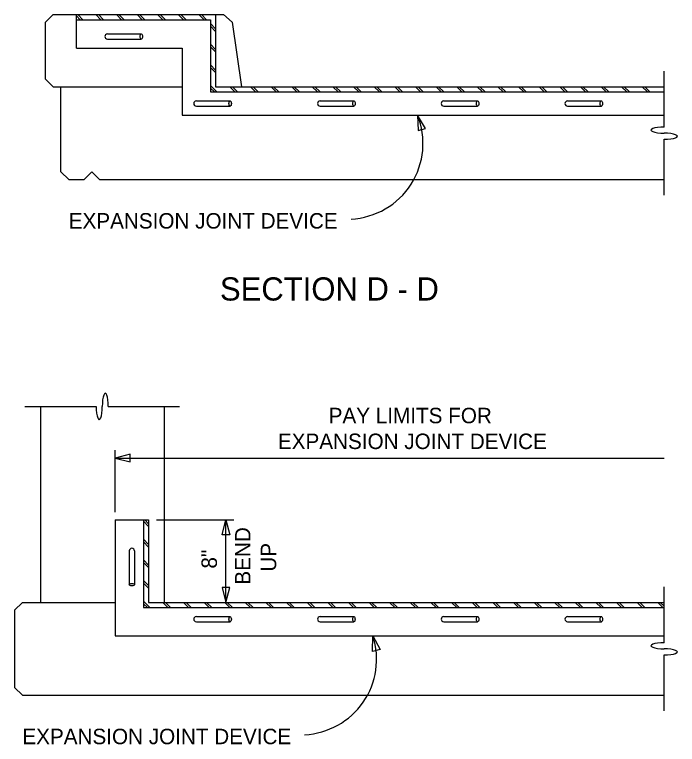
# Model space of a CAD drawing. Extents: x 19590 to 20151, y 19944 to 20103.
# Drawn here: x 19652.05 to 19671.87, y 20018.28 to 20040.1 of the extents above; entities that cross this region are included whole.
import ezdxf

# ---------------------------------------------------------------- set-up
doc = ezdxf.new("R2010")
doc.units = 0
for name, color, linetype in [('DETAIL_PR', 7, 'Continuous'), ('DETAIL_TEXT_DIMEN_PR', 7, 'Continuous'), ('Level 1', 7, 'Continuous')]:
    doc.layers.add(name, color=color, linetype=linetype)

msp = doc.modelspace()

# ---------------------------------------------------------------- linework, layer by layer
at = {"layer": 'DETAIL_PR'}
for p, q in [((19653.203, 20040.101), (19652.971, 20039.87)), ((19653.203, 20040.101), (19653.896, 20040.101)), ((19653.896, 20040.101), (19658.059, 20040.101)), ((19653.896, 20039.099), (19653.896, 20040.101)), ((19654.089, 20039.947), (19653.935, 20040.101)), ((19654.629, 20039.947), (19654.474, 20040.101)), ((19654.706, 20039.947), (19654.552, 20040.101)), ((19655.245, 20039.947), (19655.091, 20040.101)), ((19655.322, 20039.947), (19655.168, 20040.101)), ((19655.862, 20039.947), (19655.708, 20040.101)), ((19655.939, 20039.947), (19655.785, 20040.101)), ((19656.479, 20039.947), (19656.324, 20040.101)), ((19656.556, 20039.947), (19656.402, 20040.101)), ((19657.095, 20039.947), (19656.941, 20040.101)), ((19657.172, 20039.947), (19657.018, 20040.101)), ((19657.712, 20039.947), (19657.558, 20040.101)), ((19657.789, 20039.947), (19657.635, 20040.101)), ((19658.059, 20040.101), (19658.059, 20037.943)), ((19658.059, 20040.101), (19658.29, 20040.101)), ((19658.554, 20039.872), (19658.29, 20040.101)), ((19652.971, 20038.174), (19652.971, 20039.87)), ((19654.012, 20039.947), (19653.896, 20040.063)), ((19653.896, 20039.947), (19657.905, 20039.947)), ((19657.905, 20039.947), (19657.905, 20037.789)), ((19658.554, 20039.872), (19658.83, 20037.943)), ((19658.059, 20039.677), (19657.905, 20039.831)), ((19658.059, 20039.6), (19657.905, 20039.754)), ((19654.821, 20039.523), (19655.833, 20039.523)), ((19654.821, 20039.369), (19655.833, 20039.369)), ((19658.059, 20039.06), (19657.905, 20039.215)), ((19653.896, 20039.099), (19657.057, 20039.099)), ((19657.057, 20039.099), (19657.057, 20037.095)), ((19658.059, 20038.983), (19657.905, 20039.138)), ((19658.059, 20038.444), (19657.905, 20038.598)), ((19658.059, 20038.367), (19657.905, 20038.521)), ((19671.471, 20036.737), (19671.471, 20038.405)), ((19653.203, 20037.943), (19652.971, 20038.174)), ((19653.203, 20037.943), (19657.057, 20037.943)), ((19653.434, 20035.399), (19653.434, 20037.943)), ((19658.097, 20037.789), (19657.905, 20037.981)), ((19658.02, 20037.789), (19657.905, 20037.904)), ((19658.059, 20037.943), (19671.471, 20037.943)), ((19658.637, 20037.789), (19658.483, 20037.943)), ((19658.714, 20037.789), (19658.56, 20037.943)), ((19659.254, 20037.789), (19659.099, 20037.943)), ((19659.331, 20037.789), (19659.177, 20037.943)), ((19659.87, 20037.789), (19659.716, 20037.943)), ((19659.947, 20037.789), (19659.793, 20037.943)), ((19660.487, 20037.789), (19660.333, 20037.943)), ((19660.564, 20037.789), (19660.41, 20037.943)), ((19661.104, 20037.789), (19660.949, 20037.943)), ((19661.181, 20037.789), (19661.027, 20037.943)), ((19661.72, 20037.789), (19661.566, 20037.943)), ((19661.797, 20037.789), (19661.643, 20037.943)), ((19662.337, 20037.789), (19662.183, 20037.943)), ((19662.414, 20037.789), (19662.26, 20037.943)), ((19662.954, 20037.789), (19662.799, 20037.943)), ((19663.031, 20037.789), (19662.877, 20037.943)), ((19663.57, 20037.789), (19663.416, 20037.943)), ((19663.647, 20037.789), (19663.493, 20037.943)), ((19664.187, 20037.789), (19664.033, 20037.943)), ((19664.264, 20037.789), (19664.11, 20037.943)), ((19664.804, 20037.789), (19664.649, 20037.943)), ((19664.881, 20037.789), (19664.727, 20037.943)), ((19665.42, 20037.789), (19665.266, 20037.943)), ((19665.497, 20037.789), (19665.343, 20037.943)), ((19666.037, 20037.789), (19665.883, 20037.943)), ((19666.114, 20037.789), (19665.96, 20037.943)), ((19666.654, 20037.789), (19666.499, 20037.943)), ((19666.731, 20037.789), (19666.577, 20037.943)), ((19667.27, 20037.789), (19667.116, 20037.943)), ((19667.347, 20037.789), (19667.193, 20037.943)), ((19667.887, 20037.789), (19667.733, 20037.943)), ((19667.964, 20037.789), (19667.81, 20037.943)), ((19668.504, 20037.789), (19668.349, 20037.943)), ((19668.581, 20037.789), (19668.427, 20037.943)), ((19669.12, 20037.789), (19668.966, 20037.943)), ((19669.197, 20037.789), (19669.043, 20037.943)), ((19669.737, 20037.789), (19669.583, 20037.943)), ((19669.814, 20037.789), (19669.66, 20037.943)), ((19670.354, 20037.789), (19670.199, 20037.943)), ((19670.431, 20037.789), (19670.277, 20037.943)), ((19670.97, 20037.789), (19670.816, 20037.943)), ((19671.047, 20037.789), (19670.893, 20037.943)), ((19657.905, 20037.789), (19671.471, 20037.789)), ((19657.481, 20037.519), (19658.493, 20037.519)), ((19661.181, 20037.519), (19662.193, 20037.519)), ((19664.881, 20037.519), (19665.893, 20037.519)), ((19668.581, 20037.519), (19669.593, 20037.519)), ((19657.481, 20037.365), (19658.493, 20037.365)), ((19661.181, 20037.365), (19662.193, 20037.365)), ((19664.881, 20037.365), (19665.893, 20037.365)), ((19668.581, 20037.365), (19669.593, 20037.365)), ((19657.057, 20037.095), (19671.471, 20037.095)), ((19671.471, 20034.705), (19671.471, 20036.373)), ((19653.434, 20035.399), (19653.665, 20035.168)), ((19654.359, 20035.399), (19654.128, 20035.168)), ((19654.359, 20035.399), (19654.59, 20035.168)), ((19653.665, 20035.168), (19654.128, 20035.168)), ((19654.59, 20035.168), (19671.471, 20035.168)), ((19652.355, 20028.381), (19654.485, 20028.381)), ((19652.817, 20028.381), (19652.817, 20022.523)), ((19654.849, 20028.381), (19656.98, 20028.381)), ((19656.517, 20028.381), (19656.517, 20022.523)), ((19655.053, 20024.989), (19656.055, 20024.989)), ((19655.053, 20024.989), (19655.053, 20021.521)), ((19655.901, 20024.989), (19655.901, 20022.368)), ((19656.055, 20024.797), (19655.901, 20024.951)), ((19656.055, 20024.874), (19655.939, 20024.989)), ((19656.055, 20024.989), (19656.055, 20022.523)), ((19656.055, 20024.257), (19655.901, 20024.411)), ((19656.055, 20024.18), (19655.901, 20024.334)), ((19655.477, 20024.064), (19655.477, 20023.053)), ((19655.631, 20024.064), (19655.631, 20023.053)), ((19656.055, 20023.64), (19655.901, 20023.795)), ((19656.055, 20023.563), (19655.901, 20023.717)), ((19656.055, 20023.024), (19655.901, 20023.178)), ((19656.055, 20022.947), (19655.901, 20023.101)), ((19671.471, 20021.317), (19671.471, 20022.985)), ((19652.278, 20022.523), (19652.047, 20022.291)), ((19652.278, 20022.523), (19655.053, 20022.523)), ((19656.093, 20022.369), (19655.901, 20022.561)), ((19656.016, 20022.369), (19655.901, 20022.484)), ((19656.055, 20022.523), (19671.471, 20022.523)), ((19656.633, 20022.369), (19656.479, 20022.523)), ((19656.71, 20022.369), (19656.556, 20022.523)), ((19657.249, 20022.369), (19657.095, 20022.523)), ((19657.327, 20022.369), (19657.172, 20022.523)), ((19657.866, 20022.369), (19657.712, 20022.523)), ((19657.943, 20022.369), (19657.789, 20022.523)), ((19658.483, 20022.369), (19658.329, 20022.523)), ((19658.56, 20022.369), (19658.406, 20022.523)), ((19659.099, 20022.369), (19658.945, 20022.523)), ((19659.177, 20022.369), (19659.022, 20022.523)), ((19659.716, 20022.369), (19659.562, 20022.523)), ((19659.793, 20022.369), (19659.639, 20022.523)), ((19660.333, 20022.369), (19660.179, 20022.523)), ((19660.41, 20022.369), (19660.256, 20022.523)), ((19660.949, 20022.369), (19660.795, 20022.523)), ((19661.027, 20022.369), (19660.872, 20022.523)), ((19661.566, 20022.369), (19661.412, 20022.523)), ((19661.643, 20022.369), (19661.489, 20022.523)), ((19662.183, 20022.369), (19662.029, 20022.523)), ((19662.26, 20022.369), (19662.106, 20022.523)), ((19662.799, 20022.369), (19662.645, 20022.523)), ((19662.877, 20022.369), (19662.722, 20022.523)), ((19663.416, 20022.369), (19663.262, 20022.523)), ((19663.493, 20022.369), (19663.339, 20022.523)), ((19664.033, 20022.369), (19663.879, 20022.523)), ((19664.11, 20022.369), (19663.956, 20022.523)), ((19664.649, 20022.369), (19664.495, 20022.523)), ((19664.727, 20022.369), (19664.572, 20022.523)), ((19665.266, 20022.369), (19665.112, 20022.523)), ((19665.343, 20022.369), (19665.189, 20022.523)), ((19665.883, 20022.369), (19665.729, 20022.523)), ((19665.96, 20022.369), (19665.806, 20022.523)), ((19666.499, 20022.369), (19666.345, 20022.523)), ((19666.577, 20022.369), (19666.422, 20022.523)), ((19667.116, 20022.369), (19666.962, 20022.523)), ((19667.193, 20022.369), (19667.039, 20022.523)), ((19667.733, 20022.369), (19667.579, 20022.523)), ((19667.81, 20022.369), (19667.656, 20022.523)), ((19668.349, 20022.369), (19668.195, 20022.523)), ((19668.427, 20022.369), (19668.272, 20022.523)), ((19668.966, 20022.369), (19668.812, 20022.523)), ((19669.043, 20022.369), (19668.889, 20022.523)), ((19669.583, 20022.369), (19669.429, 20022.523)), ((19669.66, 20022.369), (19669.506, 20022.523)), ((19670.199, 20022.369), (19670.045, 20022.523)), ((19670.277, 20022.369), (19670.122, 20022.523)), ((19670.816, 20022.369), (19670.662, 20022.523)), ((19670.893, 20022.369), (19670.739, 20022.523)), ((19671.433, 20022.369), (19671.279, 20022.523)), ((19671.471, 20022.407), (19671.356, 20022.523)), ((19652.046, 20022.291), (19652.046, 20019.979)), ((19655.901, 20022.369), (19671.471, 20022.369)), ((19657.481, 20022.098), (19658.492, 20022.098)), ((19661.181, 20022.098), (19662.192, 20022.098)), ((19664.881, 20022.098), (19665.892, 20022.098)), ((19668.581, 20022.098), (19669.592, 20022.098)), ((19657.481, 20021.944), (19658.492, 20021.944)), ((19661.181, 20021.944), (19662.192, 20021.944)), ((19664.881, 20021.944), (19665.892, 20021.944)), ((19668.581, 20021.944), (19669.592, 20021.944)), ((19655.053, 20021.521), (19671.471, 20021.521)), ((19671.471, 20019.285), (19671.471, 20020.953)), ((19652.278, 20019.748), (19652.047, 20019.979)), ((19652.278, 20019.748), (19671.471, 20019.748))]:
    msp.add_line(p, q, dxfattribs=at)
for centre, start, end in [((19654.821, 20039.446), 90, 270), ((19657.481, 20037.442), 90, 270), ((19661.181, 20037.442), 90, 270), ((19664.881, 20037.442), 90, 270), ((19668.581, 20037.442), 90, 270), ((19655.554, 20024.064), 360, 180), ((19657.481, 20022.022), 90, 270), ((19661.181, 20022.022), 90, 270), ((19664.881, 20022.022), 90, 270), ((19668.581, 20022.022), 90, 270)]:
    msp.add_arc(centre, 0.0771, start, end, dxfattribs=at)
for centre, major_axis in [((19655.833, 20039.446), (0, 0.0773)), ((19658.493, 20037.442), (0, 0.0773)), ((19662.193, 20037.442), (0, 0.0773)), ((19665.893, 20037.442), (0, 0.0773)), ((19669.593, 20037.442), (0, 0.0773)), ((19655.554, 20023.053), (0.0773, 0)), ((19658.492, 20022.021), (0, 0.0773)), ((19662.192, 20022.021), (0, 0.0773)), ((19665.892, 20022.021), (0, 0.0773)), ((19669.592, 20022.021), (0, 0.0773))]:
    msp.add_ellipse(centre, major_axis=major_axis, ratio=0.466726, dxfattribs=at)
for centre, major_axis, ratio, start_param, end_param in [((19671.471, 20036.646), (0.395, 0), 0.230204, 1.570796, 4.712389), ((19671.471, 20036.464), (0.395, 0), 0.230206, 4.712389, 7.853982), ((19654.758, 20028.381), (0, -0.395), 0.230204, 1.570796, 4.712389), ((19654.576, 20028.381), (0, -0.395), 0.230206, 4.712389, 7.853982), ((19671.471, 20021.226), (0.395, 0), 0.230204, 1.570796, 4.712389), ((19671.471, 20021.044), (0.395, 0), 0.230206, 4.712389, 7.853982)]:
    msp.add_ellipse(centre, major_axis=major_axis, ratio=ratio, start_param=start_param, end_param=end_param, dxfattribs=at)
at = {"layer": 'DETAIL_TEXT_DIMEN_PR'}
for p, q in [((19655.053, 20025.221), (19655.053, 20027.071)), ((19655.053, 20026.839), (19671.471, 20026.839)), ((19656.286, 20024.989), (19658.599, 20024.989)), ((19658.367, 20022.523), (19658.367, 20024.989))]:
    msp.add_line(p, q, dxfattribs=at)
for centre, end in [((19661.998, 20036.246), 22.0583), ((19660.611, 20020.826), 17.8929)]:
    msp.add_arc(centre, 2.261, 272.7697, end, dxfattribs=at)
at = {"layer": 'Level 1'}
for p, q in [((19664.331, 20036.699), (19664.093, 20037.095)), ((19664.093, 20037.095), (19664.11, 20036.633)), ((19664.11, 20036.633), (19664.331, 20036.699)), ((19655.501, 20026.955), (19655.053, 20026.839)), ((19655.053, 20026.839), (19655.501, 20026.724)), ((19655.501, 20026.724), (19655.501, 20026.955)), ((19658.252, 20024.541), (19658.367, 20024.989)), ((19658.367, 20024.989), (19658.483, 20024.541)), ((19658.483, 20024.541), (19658.252, 20024.541)), ((19658.483, 20022.97), (19658.252, 20022.97)), ((19658.252, 20022.97), (19658.367, 20022.523)), ((19658.367, 20022.523), (19658.483, 20022.97)), ((19662.753, 20021.058), (19662.763, 20021.521)), ((19662.763, 20021.521), (19662.978, 20021.111)), ((19662.978, 20021.111), (19662.753, 20021.058))]:
    msp.add_line(p, q, dxfattribs=at)

# ---------------------------------------------------------------- texts
at = {"layer": 'DETAIL_TEXT_DIMEN_PR'}
for s, height, p in [('EXPANSION JOINT DEVICE', 0.4625, (19653.665, 20033.703)), ('SECTION D - D', 0.69385, (19658.187, 20031.55)), ('PAY LIMITS FOR', 0.4625, (19661.438, 20027.88)), ('EXPANSION JOINT DEVICE', 0.4625, (19659.92, 20027.109)), ('EXPANSION JOINT DEVICE', 0.4625, (19652.278, 20018.283))]:
    msp.add_text(s, height=height, dxfattribs=at).set_placement(p)
for s, p in [('BEND', (19659.1, 20023.055)), ('UP', (19659.87, 20023.442)), ('8"', (19658.097, 20023.535))]:
    msp.add_text(s, height=0.4625, rotation=90, dxfattribs=at).set_placement(p)

doc.saveas('drawing.dxf')
